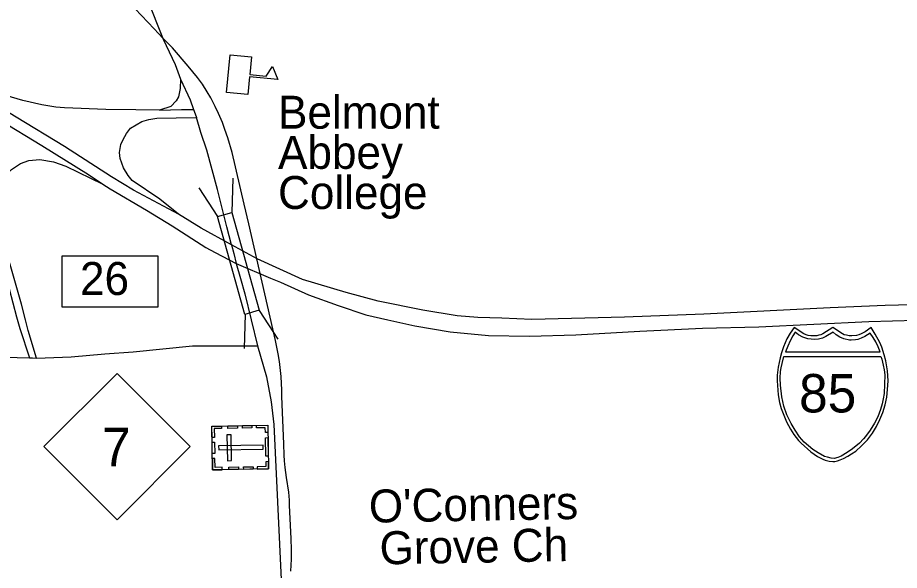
# Model space of a CAD drawing. Extents: x 1364363 to 1407445, y 538563 to 573342.
# Drawn here: x 1388956 to 1392969, y 553422 to 555939 of the extents above; entities that cross this region are included whole.
import ezdxf

# ---------------------------------------------------------------- set-up
doc = ezdxf.new("R2010")
doc.units = 0
for name, color, linetype in [('Exist Cultural Cemetery CELL', 7, 'Continuous'), ('Exist Cultural Church Label', 7, 'Continuous'), ('Exist Cultural Educational Facility College or University CELL', 7, 'Continuous'), ('Exist Cultural Educational Facility High Label', 7, 'Continuous'), ('Exist Railroad Mainline', 7, 'Continuous'), ('Exist Road Primary Interstate Divided Center Attributed', 7, 'Continuous'), ('Exist Road Primary Interstate Interchange CELL', 7, 'Continuous'), ('Exist Road Primary Interstate Ramp 1 Lane Attributed', 7, 'Continuous'), ('Exist Road Primary Interstate Shield CELL', 7, 'Continuous'), ('Exist Road Primary Interstate Shield Number Label', 7, 'Continuous'), ('Exist Road Primary NC Attributed', 7, 'Continuous'), ('Exist Road Primary NC Shield CELL', 7, 'Continuous'), ('Exist Road Primary NC Shield Number Label', 7, 'Continuous'), ('Exist Road Secondary Structure Standard Bridge CELL', 7, 'Continuous'), ('Exist Road Secondary Type 51 Attributed', 7, 'Continuous')]:
    doc.layers.add(name, color=color, linetype=linetype)

msp = doc.modelspace()

# ---------------------------------------------------------------- linework, layer by layer
at = {"layer": 'Exist Cultural Cemetery CELL'}
for points in [[(1389843.3, 553879.7), (1389839.6, 554078.8), (1390094.2, 554083.5), (1390097.9, 553884.4)], [(1389882.9, 554079.6), (1389883.1, 554068.3), (1389851, 554067.7), (1389851.7, 554027.1), (1389840.6, 554026.9), (1389839.6, 554078.8)], [(1389956.2, 554069.6), (1389912.9, 554068.8), (1389912.7, 554080.2), (1389956, 554081)], [(1390022.1, 554070.8), (1389978.8, 554070), (1389978.6, 554081.3), (1390021.9, 554082.1)], [(1390094.8, 554050.3), (1390083.3, 554050.1), (1390082.9, 554072.1), (1390042.5, 554071.4), (1390042.3, 554082.5), (1390094.2, 554083.5)], [(1389910.6, 553921.8), (1389929.2, 553922.1), (1389927.1, 554039.8), (1389908.4, 554039.5)], [(1389841.9, 553953.8), (1389841, 554005.6), (1389852.4, 554005.8), (1389853.3, 553954)], [(1389870.5, 553989.2), (1389870.9, 553970.6), (1390073.6, 553974.3), (1390073.3, 553993)], [(1390085.3, 553941.7), (1390083.7, 554026.5), (1390095.1, 554026.7), (1390096.7, 553941.9)], [(1389886.6, 553880.5), (1389886.4, 553891.8), (1389854.2, 553891.3), (1389853.4, 553931.8), (1389842.3, 553931.6), (1389843.3, 553879.7)], [(1390097.2, 553917.5), (1390085.7, 553917.3), (1390086.1, 553895.3), (1390045.7, 553894.5), (1390045.9, 553883.4), (1390097.8, 553884.4)], [(1389960.7, 553881.9), (1389917.4, 553881.1), (1389917.2, 553892.4), (1389960.5, 553893.2)], [(1390027.9, 553883.1), (1389984.6, 553882.3), (1389984.4, 553893.7), (1390027.7, 553894.5)]]:
    msp.add_lwpolyline(points, close=True, dxfattribs=at)
at = {"layer": 'Exist Cultural Educational Facility College or University CELL'}
msp.add_lwpolyline([(1389922.5, 555769.3), (1390020, 555760.3), (1390012.5, 555679.6), (1390087.3, 555672.7), (1390115.7, 555717.3), (1390139.6, 555658.2), (1390011.6, 555670), (1390004.1, 555589.4), (1389906.6, 555598.4)], close=True, dxfattribs=at)
at = {"layer": 'Exist Railroad Mainline'}
for points in [[(1389912.5, 555391.8), (1389898.9, 555430.3), (1389887.5, 555461.9), (1389869.9, 555502.7), (1389854.9, 555534.4), (1389834.5, 555573.3), (1389817.8, 555601.9), (1389796.5, 555635.8), (1389773.9, 555667.1), (1389732.6, 555718.7), (1389661.1, 555801.1), (1389617.3, 555846.4), (1389577.4, 555887.6), (1389490.8, 555978.6), (1389389.9, 556085.5), (1389222.7, 556263), (1389170.8, 556320), (1389141.7, 556350.9), (1389114.2, 556386.6), (1389096.8, 556408.8), (1389080.6, 556433.7)], [(1390199, 553419.4), (1390202.4, 553474.1), (1390201.9, 553516), (1390200, 553567.6), (1390193.5, 553718.2), (1390192.6, 553742.4), (1390190.2, 553778.3), (1390179.7, 553845.3), (1390173.4, 553890), (1390170.9, 553921), (1390169, 553946.6), (1390167, 553998.8), (1390158.1, 554214.4), (1390157.7, 554243.4), (1390154.6, 554304.4), (1390150.7, 554345.8), (1390147.2, 554372.9), (1390141.4, 554408.3), (1390129.2, 554468.4), (1390007.5, 554999.9), (1389986.8, 555089.7), (1389931.5, 555324.8), (1389912.5, 555391.8)]]:
    msp.add_lwpolyline(points, dxfattribs=at)
at = {"layer": 'Exist Road Primary Interstate Divided Center Attributed'}
for points in [[(1388172, 555892.3), (1388332.2, 555789.7), (1388515.7, 555689), (1388684.7, 555586.9), (1389066.4, 555356.2), (1389278.1, 555224.8), (1389343.7, 555181.4)], [(1389687.5, 555044.2), (1389482.6, 555154), (1389383.4, 555214.9), (1389168.3, 555351.8), (1388949.7, 555486.2), (1388735.8, 555614.6), (1388632.7, 555680.4), (1388485.7, 555774.3), (1388396.7, 555836.3)], [(1389343.7, 555181.4), (1389377.1, 555159.7), (1389542.9, 555063.2), (1389658.6, 554990.9), (1389812.5, 554892.8), (1389855.4, 554869.5), (1389950.7, 554820.1)], [(1389929.6, 554904), (1389790.5, 554980.6), (1389687.5, 555044.2)], [(1393334.1, 554650.6), (1393208.8, 554636.6), (1392904.1, 554627.7), (1392654.8, 554617.2), (1392079.2, 554588.8), (1391717.5, 554575.4), (1391295.9, 554565), (1391159.1, 554570.5), (1391050.8, 554573.9), (1390956.2, 554582), (1390800.3, 554606.6), (1390596.7, 554648.1), (1390451, 554686.9), (1390252.5, 554747.1), (1390046.2, 554841.3), (1389929.6, 554904)], [(1389950.7, 554820.1), (1390107.1, 554752.5), (1390152.2, 554734.9), (1390279.4, 554676.9), (1390414.8, 554627.7), (1390541, 554585.9), (1390641, 554563.5), (1390764.2, 554535.1), (1390924.2, 554508.2), (1391099.7, 554491.8), (1391285.9, 554488.8), (1391495.9, 554494.8), (1391787.6, 554511.9), (1392073.5, 554525), (1392329.8, 554531.6), (1392830.9, 554556.2), (1393152.9, 554564.5), (1393369.8, 554575.1)]]:
    msp.add_lwpolyline(points, dxfattribs=at)
at = {"layer": 'Exist Road Primary Interstate Interchange CELL'}
msp.add_lwpolyline([(1389158.2, 554854.7), (1389593.1, 554854.7), (1389593.1, 554621.5), (1389158.2, 554621.5)], close=True, dxfattribs=at)
at = {"layer": 'Exist Road Primary Interstate Ramp 1 Lane Attributed'}
for points in [[(1388172, 555892.3), (1388183.3, 555873.1), (1388217.5, 555843.3), (1388450.3, 555692.8), (1388543.1, 555607.5), (1388623.8, 555519.1), (1388679.8, 555428), (1388711.2, 555373.5), (1388750.7, 555280.2), (1388771.1, 555227.1), (1388830.9, 555032.5), (1388864.4, 554898.5), (1388900.9, 554768.2), (1388950.6, 554576.1), (1388965.5, 554524.2), (1389009, 554389.8)], [(1389601.7, 555518.5), (1389494.2, 555519.4), (1389356.8, 555520.3), (1389169.4, 555528.2), (1389129.8, 555532), (1389065.9, 555541.7), (1388979.7, 555562.3), (1388902.1, 555584.6), (1388844.6, 555609.6), (1388729.8, 555660.6), (1388520.3, 555780.2), (1388396.7, 555836.3)], [(1389697.4, 555658.3), (1389695.6, 555616.7), (1389687.7, 555579.2), (1389677.8, 555560.9), (1389653.2, 555533.9), (1389601.7, 555518.5)], [(1389601.7, 555518.5), (1389701.9, 555520.3), (1389756.1, 555520.3)], [(1389687.5, 555044.2), (1389602.5, 555112.9), (1389476.4, 555198), (1389458.2, 555219.6), (1389437.2, 555254.9), (1389421.9, 555297.4), (1389419.3, 555324.5), (1389426.1, 555362), (1389435.4, 555384.2), (1389450.8, 555411.8), (1389469.8, 555435.3), (1389520.4, 555466.1), (1389552.9, 555475.1), (1389589.9, 555481.4), (1389677.5, 555483.2), (1389769.7, 555484.1)], [(1389042, 554388.5), (1389003.8, 554515.1), (1388991.5, 554563.8), (1388972.6, 554635.2), (1388927.8, 554794.1), (1388892.3, 554913.8), (1388865.1, 555012.5), (1388854.8, 555085.7), (1388858.9, 555133.1), (1388873.9, 555175.3), (1388893, 555214.1), (1388927.7, 555247.5), (1388969.2, 555275.5), (1389006.7, 555289.1), (1389057.1, 555292.5), (1389119, 555282.9), (1389175.6, 555263.2), (1389343.7, 555181.4)]]:
    msp.add_lwpolyline(points, dxfattribs=at)
at = {"layer": 'Exist Road Primary Interstate Shield CELL'}
for points in [[(1392665.6, 553917.6), (1392675, 553918.5), (1392687.8, 553921), (1392700.2, 553925.1), (1392714.3, 553931.3), (1392735.1, 553942.9), (1392751.9, 553952.7), (1392771.2, 553965.7), (1392797.3, 553989.4), (1392823.4, 554016.8), (1392846.4, 554047.8), (1392864.6, 554076.8), (1392880.7, 554110), (1392894.1, 554140.9), (1392904.8, 554176.2), (1392911.8, 554210.5), (1392915.4, 554246.2), (1392917.8, 554285.7), (1392915.1, 554330.3), (1392907.4, 554375.9), (1392900.1, 554404.2), (1392889.1, 554438.1), (1392880.1, 554459.8), (1392859.2, 554498.3), (1392840.5, 554527.9), (1392813.3, 554508.7), (1392795.5, 554499.2), (1392784.7, 554494.4), (1392773.5, 554492.2), (1392753, 554489.7), (1392740.1, 554490.3), (1392728.2, 554493), (1392718, 554495.2), (1392709.8, 554499.2), (1392665.6, 554527.9), (1392621.3, 554499.2), (1392612, 554495), (1392602.5, 554493), (1392593.4, 554490.5), (1392578.2, 554489.7), (1392566.6, 554490.1), (1392554.8, 554492.2), (1392545.4, 554494.2), (1392534.9, 554499.2), (1392489.8, 554527.9), (1392472, 554502.1), (1392457.6, 554476.7), (1392442.2, 554440.8), (1392432.7, 554413), (1392425.9, 554390.1), (1392417.5, 554348.1), (1392413.2, 554311.6), (1392412.5, 554285.7), (1392417.2, 554221.2), (1392424.2, 554186.9), (1392431.5, 554159.1), (1392455.3, 554099.1), (1392473.3, 554065.4), (1392488.7, 554041.3), (1392510.3, 554014.1), (1392522, 554001.1), (1392566.8, 553962), (1392596.7, 553941.5), (1392620.6, 553928.6), (1392631.8, 553924.4), (1392649.4, 553919.4)], [(1392495.1, 554507.1), (1392484.1, 554490.2), (1392471.5, 554467.4), (1392461.3, 554443.7), (1392451, 554417.5), (1392882.5, 554417.4), (1392872.5, 554439.8), (1392861.7, 554462.3), (1392850.5, 554482.9), (1392836.8, 554502.8), (1392812.6, 554487.5), (1392794.9, 554479.2), (1392780.7, 554474.3), (1392768.8, 554471.6), (1392750.2, 554470.1), (1392741.9, 554470.6), (1392715.9, 554476.5), (1392698.4, 554483.7), (1392681.7, 554494.8), (1392668.1, 554507.6), (1392633.9, 554486.9), (1392618.8, 554480.2), (1392601.3, 554475.7), (1392582.3, 554473.3), (1392552.8, 554476.5), (1392529.8, 554484.5), (1392509.9, 554494.8)], [(1392885.1, 554396.1), (1392889.7, 554383.9), (1392896.1, 554356.8), (1392899.4, 554336), (1392902.8, 554312), (1392901.6, 554270.9), (1392899.6, 554228.3), (1392895.7, 554203.1), (1392890.5, 554180.1), (1392883.3, 554154.7), (1392871.8, 554120.8), (1392855.9, 554092.2), (1392836, 554060.4), (1392814.5, 554032.5), (1392805.2, 554020.9), (1392787.5, 554002.3), (1392755.3, 553976.4), (1392731.8, 553958.8), (1392703.6, 553942.2), (1392689.3, 553935.8), (1392672.6, 553932.3), (1392658.9, 553933.3), (1392642.3, 553937.7), (1392628.8, 553941.4), (1392599.4, 553957.3), (1392575.5, 553973.2), (1392535.8, 554005.8), (1392514.3, 554031), (1392494.3, 554060.3), (1392476.4, 554090.5), (1392457.3, 554130.1), (1392443.9, 554170), (1392434.1, 554213.1), (1392427.5, 554265.7), (1392426.8, 554297.8), (1392428.7, 554328.6), (1392431.6, 554344.8), (1392435.6, 554364.9), (1392443.4, 554395.8)]]:
    msp.add_lwpolyline(points, close=True, dxfattribs=at)
at = {"layer": 'Exist Road Primary NC Attributed'}
for points in [[(1389042, 554388.5), (1389199, 554395), (1389352.6, 554408.2), (1389481.8, 554417.1), (1389751.1, 554444), (1389911.7, 554445.4), (1390047.7, 554444.4)], [(1390047.7, 554444.4), (1390088.9, 554302.9), (1390109.7, 554190.2), (1390122, 554086.4), (1390145.2, 553605.3), (1390157.9, 553315.1), (1390164.3, 553255.8), (1390167.7, 553175.5)], [(1388610.8, 554399.2), (1388896.8, 554393.1), (1389009, 554389.8)], [(1389009, 554389.8), (1389023.9, 554389.8), (1389042, 554388.5)]]:
    msp.add_lwpolyline(points, dxfattribs=at)
at = {"layer": 'Exist Road Primary NC Shield CELL'}
msp.add_lwpolyline([(1389075.2, 553986.1), (1389408.2, 554319.1), (1389741.2, 553986.1), (1389408.2, 553653.1)], close=True, dxfattribs=at)
at = {"layer": 'Exist Road Secondary Structure Standard Bridge CELL'}
for p, q in [((1389935.2, 555208.4), (1389930.4, 555051.9)), ((1389779.7, 555164.8), (1389865.1, 555033.6)), ((1390055, 554606.3), (1390140.5, 554475.1)), ((1389991.2, 554588.4), (1389986.5, 554431.9))]:
    msp.add_line(p, q, dxfattribs=at)
msp.add_lwpolyline([(1389930.4, 555051.9), (1390055.3, 554606.4), (1389990.1, 554588.1), (1389865.1, 555033.6)], close=True, dxfattribs=at)
at = {"layer": 'Exist Road Secondary Type 51 Attributed'}
for points in [[(1390315.2, 557143.5), (1390202.8, 557076.3), (1390127.4, 557046.4), (1390050.6, 557014.4), (1389979.7, 556987.2), (1389904.8, 556950.4), (1389822.9, 556909.4), (1389776.7, 556879.5), (1389731.9, 556844.1), (1389676, 556792.4), (1389632.5, 556743.3), (1389598.6, 556689.6), (1389567.1, 556635.7), (1389537.1, 556563.5), (1389516.6, 556516.5), (1389504.3, 556461.2), (1389489.5, 556376.9), (1389488.1, 556342.8), (1389489.4, 556290.2), (1389496.3, 556199.8), (1389522.2, 556107.1), (1389543.9, 556029.5), (1389618.8, 555841.5)], [(1389618.8, 555841.5), (1389672.1, 555725.2), (1389697.4, 555658.3)], [(1389697.4, 555658.3), (1389740.8, 555565.1), (1389756.1, 555520.3)], [(1389756.1, 555520.3), (1389763.4, 555501.3), (1389769.7, 555484.1)], [(1389929.6, 554904), (1389907.9, 554986.3), (1389865.4, 555156.3), (1389816.7, 555336.2), (1389789.6, 555415.4), (1389769.7, 555484.1)], [(1389929.6, 554904), (1389939.5, 554865.2), (1389950.7, 554820.1)], [(1389950.7, 554820.1), (1389969.8, 554751.1), (1389989.5, 554681.4), (1390047.7, 554444.4)]]:
    msp.add_lwpolyline(points, dxfattribs=at)

# ---------------------------------------------------------------- texts
at = {"layer": 'Exist Cultural Church Label'}
for s, p in [("O'Conners", (1390555.7, 553639.4)), ('Grove Ch', (1390604.4, 553449.3))]:
    msp.add_text(s, height=150, rotation=1.0235, dxfattribs=at).set_placement(p)
at = {"layer": 'Exist Cultural Educational Facility High Label'}
for s, p in [('Belmont ', (1390141.1, 555433.5)), ('Abbey', (1390141.1, 555250.7)), ('College', (1390141.1, 555067.9))]:
    msp.add_text(s, height=150, dxfattribs=at).set_placement(p)
at = {"layer": 'Exist Road Primary Interstate Interchange CELL'}
msp.add_text('26', height=150, dxfattribs=at).set_placement((1389239.6, 554676.3))
at = {"layer": 'Exist Road Primary Interstate Shield Number Label'}
msp.add_text('85', height=175, dxfattribs=at).set_placement((1392512.7, 554141.4))
at = {"layer": 'Exist Road Primary NC Shield Number Label'}
msp.add_text('7', height=175, dxfattribs=at).set_placement((1389340.3, 553896.4))

doc.saveas('drawing.dxf')
